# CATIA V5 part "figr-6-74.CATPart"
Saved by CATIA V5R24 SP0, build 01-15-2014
Part number: Part2
Bounding box of the stored display mesh (mm): x -37.886 to 37.886, y -61.415 to 61.415, z 0 to 29
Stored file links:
  D:\KAVITA\CATIA V5-6R2014 Project_ Kavita\CATIA V5-6R2014_partfiles\Partfiles\c06_catia_v5-6r2014_prt\figr-6-72.CATPart
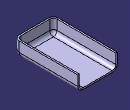
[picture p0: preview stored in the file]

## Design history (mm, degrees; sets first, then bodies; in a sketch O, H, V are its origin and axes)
Body1 (main body)
  Sketch1 on xy-plane, origin (0, 0, 0), H (1, 0, 0), V (0, 1, 0)
    line L1 (37.8862, 61.4155) -> (37.8862, -61.4155)
    line L2 (37.8862, -61.4155) -> (-37.8862, -61.4155)
    line L3 (-37.8862, -61.4155) -> (-37.8862, 61.4155)
    line L4 (-37.8862, 61.4155) -> (37.8862, 61.4155)
    vertical: L1 V, L3 V
    horizontal: L2 H, L4 H
    equidistance: L1 L3 O, L2 L4 O
  Pad1: profile Sketch1, direction (0, 0, 1), length 29
  Fillet1: radius 10, on edge [face of Pad1 | face of Pad1] (x5)
  Shell1: ExtOffset 0, Face (face of Pad1; face of Pad1), IntOffset 3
